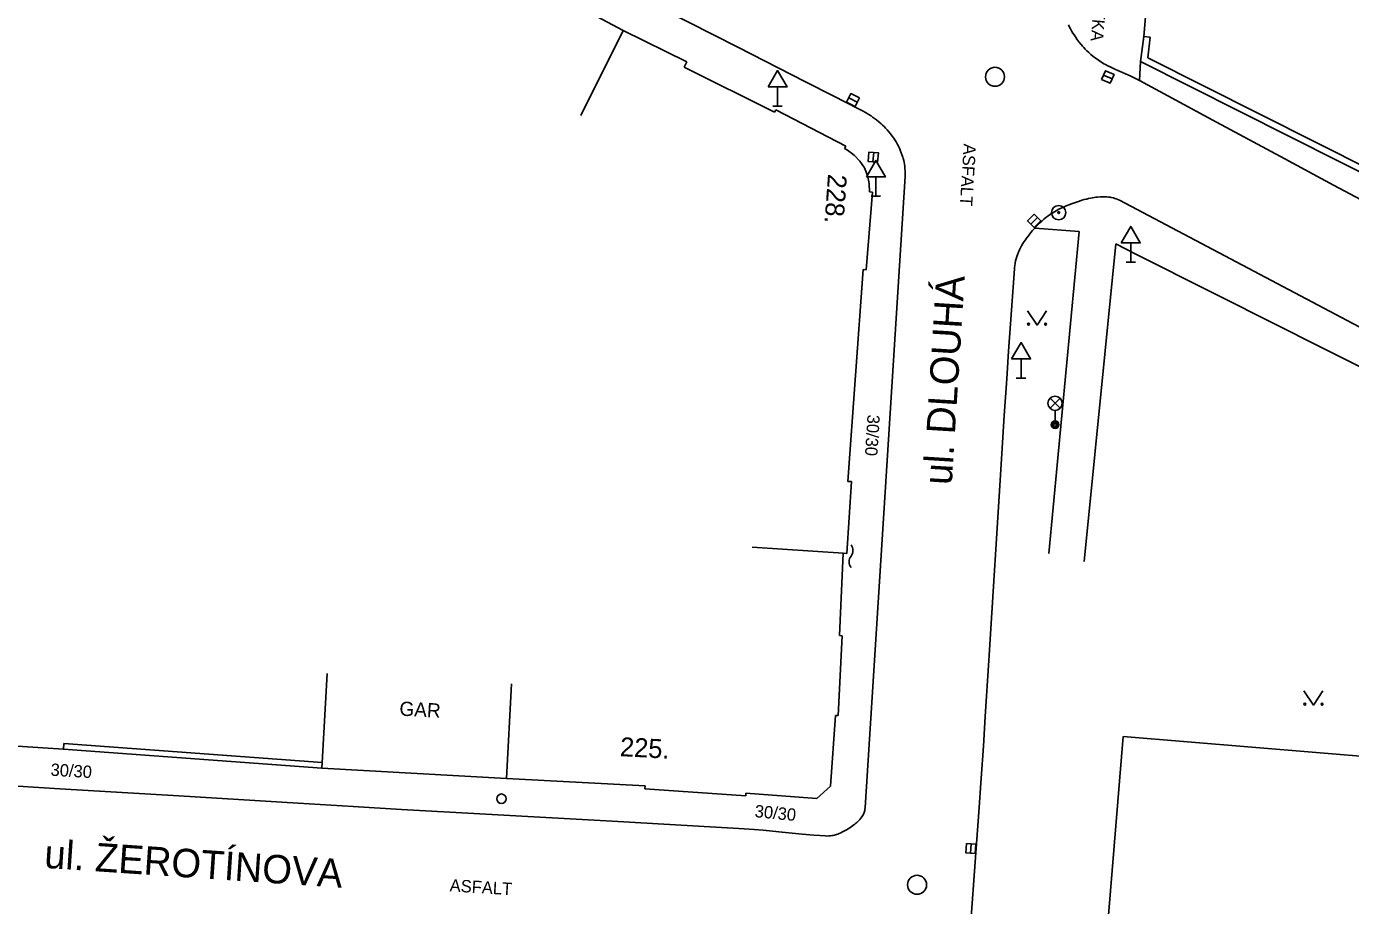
# Model space of a CAD drawing. Extents: x -538441 to -536770, y -1181008 to -1179809.
# Drawn here: x -537982.2 to -537912.6, y -1180767.2 to -1180720.9 of the extents above; entities that cross this region are included whole.
import ezdxf

# ---------------------------------------------------------------- set-up
doc = ezdxf.new("R2010")
doc.units = 0
for name, color, linetype in [('Vrstva 10', 7, 'Continuous'), ('Vrstva 11', 7, 'Continuous'), ('Vrstva 21', 7, 'Continuous'), ('Vrstva 24', 7, 'Continuous'), ('Vrstva 27', 7, 'Continuous'), ('Vrstva 28', 7, 'Continuous'), ('Vrstva 33', 7, 'Continuous'), ('Vrstva 34', 7, 'Continuous'), ('Vrstva 36', 7, 'Continuous'), ('Vrstva 40', 7, 'Continuous'), ('Vrstva 41', 7, 'Continuous'), ('Vrstva 47', 7, 'Continuous'), ('Vrstva 49', 7, 'Continuous'), ('Vrstva 5', 7, 'Continuous'), ('Vrstva 7', 7, 'Continuous'), ('Vrstva 8', 7, 'Continuous')]:
    doc.layers.add(name, color=color, linetype=linetype)

msp = doc.modelspace()

# ---------------------------------------------------------------- linework, layer by layer
at = {"layer": 'Vrstva 10'}
for p, q in [((-537944.812, -1180722.019), (-537957.29, -1180715.667)), ((-537936.535, -1180737.135), (-537936.01, -1180728.83)), ((-537924.73, -1180730.08), (-537911.835, -1180736.895)), ((-537937.06, -1180745.44), (-537936.535, -1180737.135)), ((-537931.599, -1180754.305), (-537930.956, -1180743.992)), ((-537937.585, -1180753.745), (-537937.06, -1180745.44)), ((-537938.11, -1180762.05), (-537937.585, -1180753.745)), ((-537984.65, -1180760.8), (-537980.47, -1180761.053)), ((-537980.47, -1180761.053), (-537974.2, -1180761.436)), ((-537974.2, -1180761.436), (-537967.93, -1180761.82)), ((-537958.065, -1180762.393), (-537951.413, -1180762.765)), ((-537932.967, -1180773.87), (-537932.27, -1180764.19))]:
    msp.add_line(p, q, dxfattribs=at)
for points in [[(-537916.029, -1180727.906), (-537919.852, -1180725.838), (-537921.765, -1180724.807), (-537923.68, -1180723.78), (-537923.789, -1180723.723), (-537923.995, -1180723.621), (-537924.177, -1180723.536), (-537924.82, -1180723.249), (-537924.981, -1180723.176), (-537925.221, -1180723.062), (-537925.341, -1180723.002), (-537925.46, -1180722.94), (-537925.547, -1180722.892), (-537925.63, -1180722.844), (-537925.71, -1180722.795), (-537925.862, -1180722.695), (-537926, -1180722.596), (-537926.126, -1180722.498), (-537926.242, -1180722.401), (-537926.347, -1180722.308), (-537926.443, -1180722.217), (-537926.531, -1180722.129), (-537926.611, -1180722.045), (-537926.684, -1180721.964), (-537926.75, -1180721.887), (-537926.871, -1180721.738), (-537926.971, -1180721.604), (-537927.054, -1180721.484), (-537927.124, -1180721.378), (-537927.183, -1180721.283), (-537927.232, -1180721.199), (-537927.313, -1180721.05), (-537927.37, -1180720.937), (-537927.411, -1180720.851)], [(-537939.835, -1180724.56), (-537941.25, -1180723.84), (-537944.812, -1180722.019)], [(-537936.01, -1180728.83), (-537936.004, -1180728.682), (-537936.006, -1180728.544), (-537936.014, -1180728.415), (-537936.026, -1180728.294), (-537936.042, -1180728.182), (-537936.061, -1180728.077), (-537936.082, -1180727.979), (-537936.105, -1180727.887), (-537936.129, -1180727.802), (-537936.154, -1180727.722), (-537936.207, -1180727.574), (-537936.259, -1180727.445), (-537936.309, -1180727.334), (-537936.357, -1180727.237), (-537936.401, -1180727.152), (-537936.485, -1180727.006), (-537936.552, -1180726.898), (-537936.606, -1180726.818), (-537936.69, -1180726.698), (-537936.78, -1180726.58), (-537936.87, -1180726.469), (-537936.956, -1180726.37), (-537937.038, -1180726.28), (-537937.116, -1180726.2), (-537937.19, -1180726.127), (-537937.26, -1180726.061), (-537937.394, -1180725.944), (-537937.513, -1180725.847), (-537937.62, -1180725.766), (-537937.715, -1180725.698), (-537937.799, -1180725.64), (-537937.949, -1180725.544), (-537938.064, -1180725.475), (-537938.24, -1180725.375), (-537938.42, -1180725.28), (-537939.835, -1180724.56)], [(-537908.5, -1180731.92), (-537909.454, -1180731.42), (-537910.346, -1180730.95), (-537912.017, -1180730.062), (-537913.477, -1180729.28), (-537916.029, -1180727.906)], [(-537930.417, -1180735.855), (-537930.26, -1180733.68), (-537930.253, -1180733.606), (-537930.245, -1180733.534), (-537930.224, -1180733.398), (-537930.197, -1180733.272), (-537930.167, -1180733.155), (-537930.134, -1180733.047), (-537930.099, -1180732.947), (-537930.063, -1180732.854), (-537930.026, -1180732.768), (-537929.989, -1180732.688), (-537929.953, -1180732.613), (-537929.879, -1180732.474), (-537929.809, -1180732.354), (-537929.743, -1180732.25), (-537929.683, -1180732.16), (-537929.628, -1180732.081), (-537929.526, -1180731.944), (-537929.447, -1180731.842), (-537929.322, -1180731.691), (-537929.19, -1180731.54), (-537929.126, -1180731.47), (-537929.063, -1180731.404), (-537928.94, -1180731.282), (-537928.823, -1180731.174), (-537928.711, -1180731.078), (-537928.605, -1180730.993), (-537928.504, -1180730.916), (-537928.408, -1180730.848), (-537928.318, -1180730.787), (-537928.232, -1180730.732), (-537928.068, -1180730.635), (-537927.923, -1180730.555), (-537927.794, -1180730.49), (-537927.679, -1180730.436), (-537927.578, -1180730.39), (-537927.398, -1180730.315), (-537927.261, -1180730.263), (-537927.053, -1180730.189), (-537926.84, -1180730.12), (-537926.711, -1180730.081), (-537926.588, -1180730.047), (-537926.47, -1180730.016), (-537926.359, -1180729.989), (-537926.254, -1180729.967), (-537926.155, -1180729.948), (-537926.062, -1180729.932), (-537925.975, -1180729.919), (-537925.893, -1180729.909), (-537925.74, -1180729.896), (-537925.607, -1180729.891), (-537925.491, -1180729.893), (-537925.391, -1180729.898), (-537925.304, -1180729.907), (-537925.229, -1180729.918), (-537925.163, -1180729.929), (-537925.051, -1180729.955), (-537924.968, -1180729.98), (-537924.907, -1180730.001), (-537924.818, -1180730.037), (-537924.73, -1180730.08)], [(-537930.956, -1180743.992), (-537930.792, -1180741.413), (-537930.665, -1180739.48), (-537930.568, -1180738.03), (-537930.417, -1180735.855)], [(-537932.27, -1180764.19), (-537932.132, -1180762.284), (-537932.006, -1180760.497), (-537931.893, -1180758.822), (-537931.789, -1180757.251), (-537931.599, -1180754.305)], [(-537967.93, -1180761.82), (-537965.034, -1180761.993), (-537962.5, -1180762.141), (-537958.065, -1180762.393)], [(-537942.649, -1180763.316), (-537941.419, -1180763.437), (-537940.805, -1180763.492), (-537940.497, -1180763.517), (-537940.19, -1180763.54), (-537940.133, -1180763.543), (-537940.027, -1180763.542), (-537939.935, -1180763.535), (-537939.855, -1180763.524), (-537939.785, -1180763.51), (-537939.724, -1180763.496), (-537939.618, -1180763.465), (-537939.538, -1180763.437), (-537939.479, -1180763.414), (-537939.389, -1180763.374), (-537939.3, -1180763.33), (-537939.195, -1180763.274), (-537939.096, -1180763.218), (-537939.004, -1180763.164), (-537938.919, -1180763.112), (-537938.841, -1180763.061), (-537938.769, -1180763.011), (-537938.704, -1180762.963), (-537938.645, -1180762.916), (-537938.591, -1180762.872), (-537938.542, -1180762.829), (-537938.455, -1180762.745), (-537938.385, -1180762.669), (-537938.329, -1180762.6), (-537938.284, -1180762.538), (-537938.249, -1180762.482), (-537938.221, -1180762.432), (-537938.198, -1180762.387), (-537938.165, -1180762.307), (-537938.144, -1180762.245), (-537938.132, -1180762.198), (-537938.118, -1180762.125), (-537938.11, -1180762.05)], [(-537951.413, -1180762.765), (-537948.086, -1180762.951), (-537944.76, -1180763.14), (-537944.474, -1180763.158), (-537943.938, -1180763.197), (-537943.469, -1180763.238), (-537942.649, -1180763.316)]]:
    msp.add_lwpolyline(points, dxfattribs=at)
at = {"layer": 'Vrstva 11'}
for p, q in [((-537923.62, -1180722.78), (-537923.68, -1180723.78)), ((-537929.19, -1180731.54), (-537926.86, -1180731.73)), ((-537926.86, -1180731.73), (-537928.455, -1180748.67)), ((-537924.93, -1180732.37), (-537926.585, -1180749.095)), ((-537914.01, -1180737.876), (-537919.477, -1180735.135))]:
    msp.add_line(p, q, dxfattribs=at)
for points in [[(-537919.477, -1180735.135), (-537920.843, -1180734.448), (-537922.889, -1180733.413), (-537923.91, -1180732.893), (-537924.93, -1180732.37)], [(-537905.271, -1180742.364), (-537906.49, -1180741.722), (-537907.635, -1180741.124), (-537908.711, -1180740.568), (-537909.721, -1180740.049), (-537910.67, -1180739.565), (-537912.45, -1180738.662), (-537914.01, -1180737.876)]]:
    msp.add_lwpolyline(points, dxfattribs=at)
at = {"layer": 'Vrstva 21'}
for radius in [0.375, 0.05]:
    msp.add_circle((-537927.93, -1180730.73), radius, dxfattribs=at)
at = {"layer": 'Vrstva 24'}
for centre, start, end in [((-537939.25, -1180748.51), 323.1301, 36.8699), ((-537938.45, -1180749.11), 143.1301, 216.8699)]:
    msp.add_arc(centre, 0.5, start, end, dxfattribs=at)
at = {"layer": 'Vrstva 27'}
for p, q in [((-537925.578, -1180723.487), (-537925.122, -1180723.693)), ((-537938.527, -1180724.913), (-537938.973, -1180724.687)), ((-537937.7, -1180728.059), (-537937.66, -1180727.561)), ((-537929.401, -1180731.343), (-537929.047, -1180730.989)), ((-537932.537, -1180763.948), (-537932.573, -1180764.446))]:
    msp.add_line(p, q, dxfattribs=at)
for points in [[(-537925.681, -1180723.715), (-537925.225, -1180723.921), (-537925.019, -1180723.465), (-537925.475, -1180723.259)], [(-537938.414, -1180724.69), (-537938.86, -1180724.464), (-537939.086, -1180724.91), (-537938.64, -1180725.136)], [(-537937.451, -1180728.079), (-537937.411, -1180727.581), (-537937.909, -1180727.541), (-537937.949, -1180728.039)], [(-537929.223, -1180731.52), (-537928.87, -1180731.165), (-537929.225, -1180730.812), (-537929.578, -1180731.167)], [(-537932.786, -1180763.93), (-537932.822, -1180764.428), (-537932.324, -1180764.464), (-537932.288, -1180763.966)]]:
    msp.add_lwpolyline(points, close=True, dxfattribs=at)
for centre in [(-537931.28, -1180723.58), (-537935.38, -1180766.11)]:
    msp.add_circle(centre, 0.5, dxfattribs=at)
at = {"layer": 'Vrstva 28'}
msp.add_circle((-537957.24, -1180761.58), 0.25, dxfattribs=at)
at = {"layer": 'Vrstva 33'}
for p, q in [((-537928.385, -1180741.03), (-537927.855, -1180740.5)), ((-537928.385, -1180740.5), (-537927.855, -1180741.03)), ((-537928.12, -1180741.14), (-537928.12, -1180741.89))]:
    msp.add_line(p, q, dxfattribs=at)
for centre, radius in [((-537928.12, -1180740.765), 0.375), ((-537928.12, -1180741.89), 0.2), ((-537928.12, -1180741.89), 0.145), ((-537928.12, -1180741.89), 0.0876)]:
    msp.add_circle(centre, radius, dxfattribs=at)
at = {"layer": 'Vrstva 34'}
for p, q in [((-537942.717, -1180724.115), (-537942.717, -1180725.133)), ((-537942.967, -1180725.133), (-537942.467, -1180725.133)), ((-537937.547, -1180728.847), (-537937.547, -1180729.865)), ((-537937.797, -1180729.865), (-537937.297, -1180729.865)), ((-537924.137, -1180732.321), (-537924.137, -1180733.339)), ((-537924.387, -1180733.339), (-537923.887, -1180733.339)), ((-537929.911, -1180738.432), (-537929.911, -1180739.45)), ((-537930.161, -1180739.45), (-537929.661, -1180739.45))]:
    msp.add_line(p, q, dxfattribs=at)
for points in [[(-537943.217, -1180724.115), (-537942.217, -1180724.115), (-537942.717, -1180723.249)], [(-537938.047, -1180728.847), (-537937.047, -1180728.847), (-537937.547, -1180727.981)], [(-537924.637, -1180732.321), (-537923.637, -1180732.321), (-537924.137, -1180731.455)], [(-537930.411, -1180738.432), (-537929.411, -1180738.432), (-537929.911, -1180737.566)]]:
    msp.add_lwpolyline(points, close=True, dxfattribs=at)
at = {"layer": 'Vrstva 36'}
for points in [[(-537929.565, -1180735.897), (-537929.065, -1180736.647), (-537928.564, -1180735.897)], [(-537915.029, -1180755.898), (-537914.529, -1180756.648), (-537914.028, -1180755.898)]]:
    msp.add_lwpolyline(points, dxfattribs=at)
for centre in [(-537929.515, -1180736.597), (-537928.616, -1180736.597), (-537914.979, -1180756.598), (-537914.08, -1180756.598)]:
    msp.add_circle(centre, 0.05, dxfattribs=at)
at = {"layer": 'Vrstva 5'}
for p, q in [((-537950.83, -1180721.14), (-537960.55, -1180715.96)), ((-537953.055, -1180725.617), (-537950.83, -1180721.14)), ((-537947.49, -1180722.8), (-537950.83, -1180721.14)), ((-537947.63, -1180723.081), (-537947.49, -1180722.8)), ((-537947.63, -1180723.081), (-537942.879, -1180725.442)), ((-537942.879, -1180725.442), (-537942.81, -1180725.31)), ((-537942.81, -1180725.31), (-537939.13, -1180727.23)), ((-537939.199, -1180727.362), (-537939.13, -1180727.23)), ((-537938.06, -1180733.74), (-537937.73, -1180729.65)), ((-537937.879, -1180729.638), (-537937.73, -1180729.65)), ((-537938.209, -1180733.728), (-537939.019, -1180744.877)), ((-537938.209, -1180733.728), (-537938.06, -1180733.74)), ((-537939.07, -1180748.67), (-537938.82, -1180744.89)), ((-537939.019, -1180744.877), (-537938.82, -1180744.89)), ((-537939.269, -1180748.656), (-537939.459, -1180752.993)), ((-537939.52, -1180757.2), (-537939.31, -1180753)), ((-537939.459, -1180752.993), (-537939.31, -1180753)), ((-537956.702, -1180755.528), (-537956.98, -1180760.52)), ((-537939.669, -1180757.193), (-537939.93, -1180760.92)), ((-537939.669, -1180757.193), (-537939.52, -1180757.2)), ((-537924.53, -1180758.3), (-537929, -1180812.18)), ((-537910.103, -1180759.497), (-537924.53, -1180758.3)), ((-537966.68, -1180759.98), (-537956.98, -1180760.52)), ((-537949.68, -1180760.91), (-537956.98, -1180760.52)), ((-537949.68, -1180760.91), (-537949.69, -1180761.06)), ((-537949.69, -1180761.06), (-537944.39, -1180761.43)), ((-537940.65, -1180761.57), (-537939.93, -1180760.92)), ((-537944.38, -1180761.28), (-537944.39, -1180761.43)), ((-537940.65, -1180761.57), (-537944.38, -1180761.28))]:
    msp.add_line(p, q, dxfattribs=at)
for points in [[(-537937.879, -1180729.638), (-537937.891, -1180729.204), (-537937.982, -1180728.779), (-537938.15, -1180728.378), (-537938.388, -1180728.014), (-537938.688, -1180727.7), (-537939.041, -1180727.447), (-537939.199, -1180727.362)], [(-537944.059, -1180748.34), (-537939.269, -1180748.656), (-537939.07, -1180748.67)], [(-537966.402, -1180754.988), (-537966.663, -1180759.681), (-537966.68, -1180759.98)]]:
    msp.add_lwpolyline(points, dxfattribs=at)
at = {"layer": 'Vrstva 7'}
for p, q in [((-537923.243, -1180722.578), (-537923.113, -1180721.492)), ((-537966.663, -1180759.681), (-537980.258, -1180758.681))]:
    msp.add_line(p, q, dxfattribs=at)
for points in [[(-537923.62, -1180722.78), (-537923.46, -1180721.45), (-537923.113, -1180721.492)], [(-537896.82, -1180736.28), (-537902.698, -1180733.319), (-537923.62, -1180722.78)], [(-537896.648, -1180735.975), (-537902.648, -1180732.952), (-537923.243, -1180722.578)], [(-537980.258, -1180758.681), (-537980.28, -1180758.98), (-537966.68, -1180759.98)]]:
    msp.add_lwpolyline(points, dxfattribs=at)
at = {"layer": 'Vrstva 8'}
for p, q in [((-537923.19, -1180718.32), (-537923.46, -1180721.45)), ((-537985.2, -1180758.64), (-537980.28, -1180758.98))]:
    msp.add_line(p, q, dxfattribs=at)

# ---------------------------------------------------------------- texts
at = {"layer": 'Vrstva 40'}
for s, rotation, p in [('KOSTKA', 265.06976, (-537925.944, -1180718.168)), ('ASFALT', 266.38286, (-537932.922, -1180727.09)), ('30/30', 266.38286, (-537937.983, -1180741.347)), ('30/30', 356.52654, (-537980.969, -1180760.366)), ('30/30', 354.34817, (-537943.942, -1180762.543)), ('ASFALT', 356.43996, (-537959.975, -1180766.455))]:
    msp.add_text(s, height=0.65, rotation=rotation, dxfattribs=at).set_placement(p)
at = {"layer": 'Vrstva 41'}
msp.add_text('GAR', height=0.75, rotation=356.81363, dxfattribs=at).set_placement((-537962.622, -1180757.202))
at = {"layer": 'Vrstva 47'}
for s, rotation, p in [('228.', 265.84463, (-537940.059, -1180728.678)), ('225.', 356.9419, (-537951.023, -1180759.336))]:
    msp.add_text(s, height=1, rotation=rotation, dxfattribs=at).set_placement(p)
at = {"layer": 'Vrstva 49'}
for s, rotation, p in [('ul. DLOUHÁ', 86.42832, (-537933.558, -1180745.089)), ('ul. ŽEROTÍNOVA', 356.16437, (-537981.316, -1180765.216))]:
    msp.add_text(s, height=1.5, rotation=rotation, dxfattribs=at).set_placement(p)

doc.saveas('drawing.dxf')
